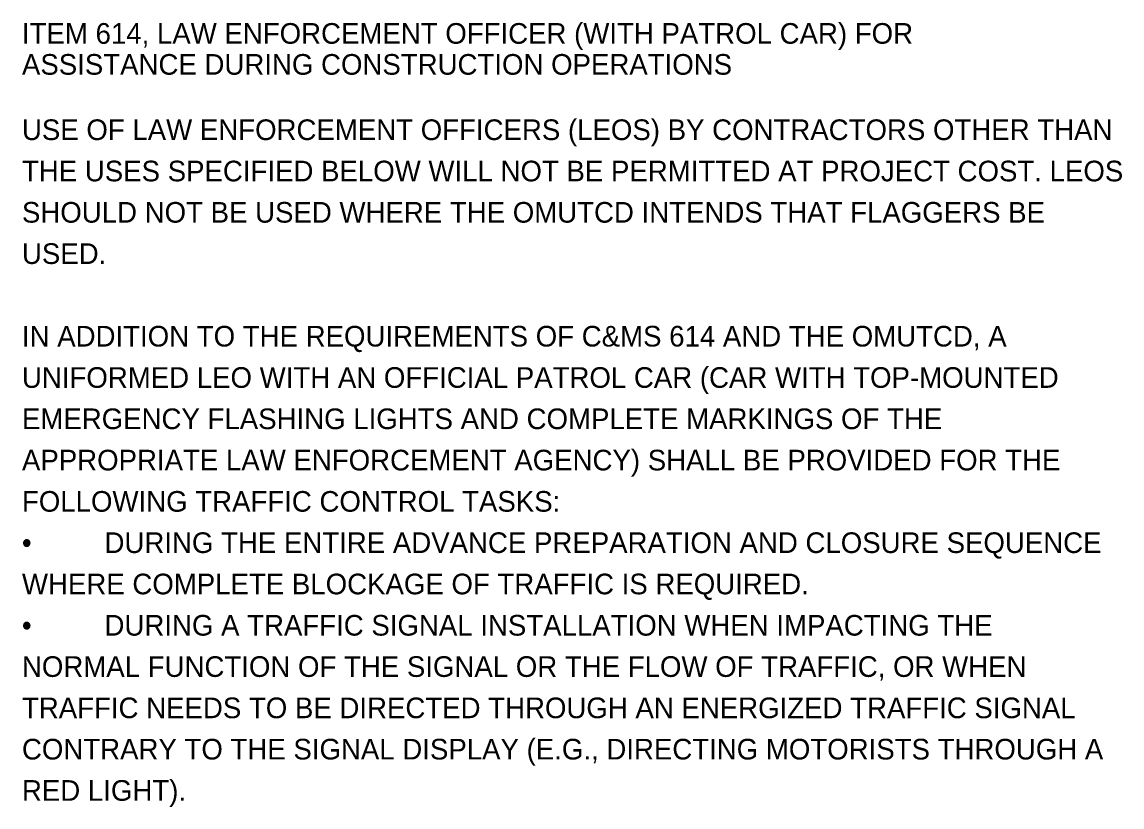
# Model space of a CAD drawing. Extents: x 0 to 53.7, y -25.8 to 22.
# Drawn here: x 35.67 to 43.13, y 4.24 to 9.56 of the extents above; entities that cross this region are included whole.
import ezdxf

# ---------------------------------------------------------------- set-up
doc = ezdxf.new("R2010")
doc.units = 0
doc.layers.add('SH_Text', color=7, linetype='Continuous')

msp = doc.modelspace()

# ---------------------------------------------------------------- texts
at = {"layer": 'SH_Text'}
for s, p in [('ITEM 614, LAW ENFORCEMENT OFFICER (WITH PATROL CAR) FOR ', (35.6716, 9.4137)), ('ASSISTANCE DURING CONSTRUCTION OPERATIONS', (35.6716, 9.2037)), ('USE OF LAW ENFORCEMENT OFFICERS (LEOS) BY CONTRACTORS OTHER THAN ', (35.6716, 8.7607)), ('THE USES SPECIFIED BELOW WILL NOT BE PERMITTED AT PROJECT COST. LEOS ', (35.6716, 8.4807)), ('SHOULD NOT BE USED WHERE THE OMUTCD INTENDS THAT FLAGGERS BE ', (35.6716, 8.2007)), ('USED.', (35.6716, 7.9207)), ('IN ADDITION TO THE REQUIREMENTS OF C&MS 614 AND THE OMUTCD, A ', (35.6716, 7.3607)), ('UNIFORMED LEO WITH AN OFFICIAL PATROL CAR (CAR WITH TOP-MOUNTED ', (35.6716, 7.0807)), ('EMERGENCY FLASHING LIGHTS AND COMPLETE MARKINGS OF THE ', (35.6716, 6.8007)), ('APPROPRIATE LAW ENFORCEMENT AGENCY) SHALL BE PROVIDED FOR THE ', (35.6716, 6.5207)), ('FOLLOWING TRAFFIC CONTROL TASKS:', (35.6716, 6.2407)), ('•', (35.6716, 5.9607)), ('DURING THE ENTIRE ADVANCE PREPARATION AND CLOSURE SEQUENCE ', (36.2316, 5.9607)), ('WHERE COMPLETE BLOCKAGE OF TRAFFIC IS REQUIRED. ', (35.6716, 5.6807)), ('DURING A TRAFFIC SIGNAL INSTALLATION WHEN IMPACTING THE ', (36.2316, 5.4007)), ('•', (35.6716, 5.4007)), ('NORMAL FUNCTION OF THE SIGNAL OR THE FLOW OF TRAFFIC, OR WHEN ', (35.6716, 5.1207)), ('TRAFFIC NEEDS TO BE DIRECTED THROUGH AN ENERGIZED TRAFFIC SIGNAL ', (35.6716, 4.8407)), ('CONTRARY TO THE SIGNAL DISPLAY (E.G., DIRECTING MOTORISTS THROUGH A ', (35.6716, 4.5607)), ('RED LIGHT). ', (35.6716, 4.2807))]:
    msp.add_text(s, height=0.14, dxfattribs=at).set_placement(p)

doc.saveas('drawing.dxf')
